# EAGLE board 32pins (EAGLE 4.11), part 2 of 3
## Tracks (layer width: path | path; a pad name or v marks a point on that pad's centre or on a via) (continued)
GND  (via drill 0.61) (continued)
  Top 0.254: 35.55,126.2 35.55,133.19 C2.2 | 35.55,126.2 35.55,122.39 D38.A | 35.55,126.2 40,121.75 D39.A 41.27,121.75 42.54,120.48 43.81,120.48 45.08,119.21 R135.1 45.71,118.58 46.35,117.94 49.52,117.94 50.16,118.58 50.79,118.58 R131.1 | 17.78,67.78 17.78,63.97 D19.A 18.41,63.34 19.68,62.06 20.95,62.06 | 17.78,67.78 D24.A | 20.95,62.06 22.22,60.8 R55.1 | 20.95,62.06 26.67,62.06 27.3,61.43 27.3,60.8 R51.1 | 17.78,67.78 D24.A | R79.1 30.48,70.32 29.84,69.68 27.3,69.68 26.03,68.41 R75.1 24.76,68.41 23.49,67.14 19.68,67.14 18.41,68.41 D24.A | 35.55,65.24 35.55,67.78 D29.A | 35.55,65.24 35.55,63.97 D22.A | 40.63,65.24 40.63,67.78 D28.A | 40.63,65.24 40.63,63.97 D23.A | 43.81,62.06 45.08,60.8 R71.1 | 43.81,62.06 42.54,62.06 41.27,63.34 | D23.A 41.27,63.34 | 43.81,62.06 49.52,62.06 50.16,61.43 50.16,60.8 R67.1 | 41.27,63.34 47.62,69.68 | 47.62,69.68 48.25,70.32 R91.1 | D23.A 41.27,63.34 | 47.62,69.68 52.06,69.68 52.7,70.32 53.34,70.32 R95.1 | 35.55,65.24 40.63,65.24 | 17.78,95.72 17.78,98.26 D32.A 18.41,98.89 19.68,97.62 21.59,97.62 R107.1 25.39,100.8 26.03,100.8 26.67,100.16 29.84,100.16 30.48,100.8 R111.1 | 17.78,95.72 17.78,91.91 D27.A 18.41,91.27 19.68,90 20.95,90 22.22,88.73 R87.1 | 17.78,95.72 13.33,91.27 D26.A 12.69,90.64 10.79,88.73 10.79,70.95 12.69,69.05 D25.A | 35.55,95.72 35.55,98.26 D37.A | 35.55,95.72 35.55,91.91 D30.A | 35.55,95.72 40,91.27 D31.A 41.27,91.27 42.54,90 43.81,90 | 47.62,100.16 45.08,97.62 42.54,97.62 41.27,98.89 D36.A | 47.62,100.16 48.25,100.8 R123.1 | 47.62,100.16 52.06,100.16 52.7,100.8 53.34,100.8 R127.1 | v11.42,106.52 11.42,100.8 12.69,99.53 D33.A | v147.95,35.4 146.05,35.4 145.41,34.76 137.16,34.76 135.88,33.49 134.62,33.49 v130.17,37.94
  Top 0.254: v125.73,37.94 v125.73,48.73 | v116.84,57.62 v116.84,62.7 | 168.91,149.06 175.25,142.71 GND.1 | 43.81,90 45.08,88.73 R103.1 | 43.81,90 49.52,90 50.16,89.37 50.16,88.73 R99.1
  Bottom 0.254: IC9.GND 195.58,128.11 195.58,135.09 185.41,145.25 185.41,145.89 IC10.GND | Q51.S 156.84,45.55 154.94,43.65 D84.A 154.94,42.38 151.12,42.38 149.86,41.11 R276.2 | R11.2 150.49,10 152.4,11.9 154.94,11.9 D6.A | R274.2 130.17,40.48 132.08,42.38 134.62,42.38 D82.A | D75.A 139.69,18.25 139.69,24.6 R272.2 139.69,25.87 139.69,27.14 | D79.A 139.69,33.49 139.69,39.84 R282.2 140.33,40.48 141.6,41.74 142.87,41.74 144.14,43.02 D90.A | R264.2 130.17,25.23 132.08,27.14 134.62,27.14 D72.A | 139.69,27.14 137.16,29.68 Q39.S | D76.A 144.14,12.54 142.87,11.27 141.6,11.27 140.33,10 R268.2 | 139.69,27.14 143.5,27.14 144.14,27.78 D80.A | D107.A 160.02,75.4 158.11,73.49 Q73.S | D99.A 139.69,76.67 139.69,83.02 R296.2 139.69,84.29 139.69,85.56 137.16,88.1 Q69.S | D105.A 149.86,75.4 147.95,73.49 Q67.S 147.31,72.86 149.86,70.32 149.86,69.05 R298.2 | R278.2 130.17,55.72 132.08,57.62 134.62,57.62 D86.A | 140.97,69.05 140.33,68.41 R292.2 | 140.97,69.05 142.87,70.95 144.14,70.95 D100.A | 140.97,69.05 137.16,72.86 Q65.S | R302.2 150.49,83.65 152.4,85.56 154.94,85.56 D110.A | 139.69,93.81 139.69,91.91 D103.A | 139.69,93.81 139.69,98.26 R308.2 | R294.2 130.17,83.65 132.08,85.56 134.62,85.56 D102.A | 139.69,93.81 146.68,93.81 149.22,91.27 D109.A | D117.A 130.17,121.75 131.44,123.02 137.79,123.02 139.06,121.75 D125.A | R310.2 130.17,114.13 132.08,116.04 134.62,116.04 D118.A | D115.A 139.69,107.15 139.69,113.5 R318.2 139.69,114.77 139.69,116.04 | R306.2 130.17,98.89 132.08,100.8 134.62,100.8 D114.A | 139.69,116.04 137.16,118.58 Q85.S | D121.A 149.86,107.15 149.86,113.5 R312.2 149.86,114.77 149.86,116.04
  Bottom 0.254: 149.86,116.04 147.31,118.58 Q93.S | D122.A 154.3,101.43 153.03,100.16 151.76,100.16 150.49,98.89 R314.2 | 149.86,116.04 153.66,116.04 154.3,116.67 D120.A | 139.69,116.04 144.78,116.04 D126.A | 89.53,44.29 90.8,43.02 D47.A | 89.53,44.29 86.99,46.83 83.18,46.83 81.91,45.55 R166.2 | 89.53,44.29 94.61,44.29 95.88,45.55 100.96,45.55 R170.2 | R150.2 81.91,30.32 83.18,31.59 89.53,31.59 90.8,30.32 R162.2 | R146.2 100.96,30.32 95.88,30.32 94.61,29.05 93.34,29.05 92.07,27.78 D42.A | 89.53,13.81 90.8,12.54 D1.A | 89.53,13.81 86.99,16.35 83.18,16.35 81.91,15.08 R142.2 | 89.53,13.81 94.61,13.81 95.88,15.08 100.96,15.08 R154.2 | D40.A 102.23,12.54 103.5,13.81 106.04,13.81 107.31,15.08 111.12,15.08 R14.2 | D5.A 102.23,27.78 103.5,29.05 106.04,29.05 107.31,30.32 111.12,30.32 R158.2 | D44.A 102.23,43.02 103.5,44.29 106.04,44.29 107.31,45.55 111.12,45.55 R186.2 | 80.64,62.06 80.01,62.7 80.01,69.05 81.28,70.32 D51.A | 80.64,62.06 81.28,61.43 R174.2 | 80.64,62.06 84.45,62.06 85.72,60.8 90.8,60.8 R190.2 92.07,60.8 93.34,59.52 94.61,59.52 95.88,60.8 100.96,60.8 R178.2 | 99.69,74.77 93.34,74.77 92.07,73.49 R214.2 | 99.69,74.77 100.96,73.49 R202.2 | 99.69,74.77 104.77,74.77 106.04,73.49 111.12,73.49 R218.2 | D61.A 81.91,116.67 83.18,115.4 85.72,115.4 86.99,114.13 88.26,114.13 90.8,116.67 D65.A | 94.61,120.48 95.88,119.21 100.96,119.21 R242.2 | 94.61,120.48 93.34,120.48 92.07,119.21 R254.2 | 94.61,120.48 104.77,120.48 106.04,119.21 111.12,119.21 R258.2 | 89.53,90 87.62,90 | 87.62,90 83.18,90 81.91,88.73 R206.2 | 89.53,90 90.8,88.73 R222.2 | 89.53,90 94.61,90 95.88,88.73 100.96,88.73 R210.2
  Bottom 0.254: 82.55,104.61 83.18,105.24 86.99,105.24 90.8,101.43 D63.A | 82.55,104.61 81.91,103.97 R230.2 | 110.48,104.61 111.12,103.97 R250.2 | 110.48,104.61 109.85,105.24 103.5,105.24 102.23,103.97 R234.2 | R246.2 92.07,103.97 93.34,105.24 97.15,105.24 100.96,101.43 D60.A | 87.62,90 87.62,93.18 82.55,98.26 82.55,104.61 | 110.48,104.61 v110.48,107.78 | R226.2 111.12,88.73 106.04,88.73 104.77,87.46 103.5,87.46 102.23,86.19 D54.A | R1.1 25.39,11.9 22.22,8.73 19.68,8.73 18.41,10 D2.A | D12.A 40,10 38.73,11.27 37.46,11.27 36.19,10 D13.A | R47.1 31.11,43.02 33.65,40.48 34.92,40.48 D21.A | R115.1 28.57,119.21 28.57,119.85 29.21,120.48 33.65,120.48 34.92,121.75 D38.A | D18.A 12.69,63.97 12.69,67.78 D25.A | R79.1 31.11,70.95 33.65,68.41 34.92,68.41 D29.A | D26.A 12.69,91.91 12.69,98.26 D33.A | R83.1 27.94,88.1 27.3,88.1 26.67,87.46 23.49,87.46 22.86,88.1 R87.1 | D36.A 40,98.89 38.73,100.16 37.46,100.16 36.19,98.89 D37.A 34.92,98.89 33.65,98.89 31.11,101.43 R111.1 | v11.42,106.52 11.42,119.85 12.69,121.12 D34.A | v59.05,8.73 57.78,8.73 53.97,12.54 R31.1 | v147.95,35.4 149.86,33.49 D69.A | v130.17,37.94 v125.73,37.94 | v125.73,48.73 v116.84,57.62 | v116.84,62.7 112.39,58.26 D50.A
  pour Top (rank 2): 200.66,129.38 190.5,129.38 190.5,144.62 200.66,144.62
H1  (via drill 0.61)
  Top 0.254: 105.41,24.6 104.14,23.33 64.13,23.33 54.6,32.86 53.97,32.86 R36.1 | 105.41,24.6 107.31,26.51 Q9.D | Q46.D 160.65,29.05 161.92,27.78 163.19,27.78 165.09,29.68 Q45.D | v183.51,31.59 182.24,31.59 179.7,29.05 167,29.05 166.37,28.41 v166.37,26.51 | v106.04,23.96 105.41,24.6 | v118.74,15.08 127,6.82 167.63,6.82 185.41,24.6 189.22,24.6 190.5,25.87 v190.5,36.03
  Bottom 0.254: 189.22,37.3 188.59,36.66 183.51,36.66 180.97,34.12 v183.51,31.59 | 189.22,37.3 193.03,41.11 193.03,105.88 170.81,128.11 167,128.11 165.09,130.01 127,130.01 120.65,136.36 120.65,137.63 119.38,138.9 SIDE1.16 | v166.37,26.51 166.37,24.6 165.09,23.33 162.56,23.33 161.28,24.6 161.28,27.14 160.02,28.41 Q46.D | v106.04,23.96 109.85,23.96 v118.74,15.08 | 189.22,37.3 v190.5,36.03
H2  (via drill 0.61)
  Top 0.254: 67.31,72.86 73.02,67.14 84.45,67.14 86.99,69.68 Q23.D 87.62,69.05 v89.53,67.14 | 67.31,72.86 66.04,74.13 62.22,74.13 55.24,67.14 50.16,67.14 48.89,68.41 R92.1 | v63.49,125.56 64.77,125.56 v67.94,122.39 | 67.31,72.86 v73.02,78.57 | v146.05,64.6 v148.59,67.14 | v118.11,71.59 v125.09,64.6
  Bottom 0.254: 154.94,72.86 153.03,70.95 151.76,70.95 150.49,72.22 Q74.D | 154.94,72.86 Q73.D 154.94,72.86 | v63.49,125.56 59.68,129.38 59.68,137.63 58.41,138.9 SIDE2.12 | v67.94,122.39 67.94,117.94 78.1,107.78 79.37,107.78 80.01,107.15 80.01,98.26 74.93,93.18 74.93,90.64 74.29,90 73.02,90 72.39,89.37 72.39,79.21 v73.02,78.57 | 154.94,72.86 156.21,71.59 156.21,67.78 155.57,67.14 v148.59,67.14 | v125.09,64.6 v146.05,64.6 | v118.11,71.59 113.03,66.51 90.17,66.51 v89.53,67.14
J1  (via drill 0.61)
  Top 0.254: v66.67,25.23 64.77,27.14 64.77,30.95 64.13,31.59 58.41,31.59 56.51,33.49 54.6,33.49 53.97,34.12 50.16,34.12 48.89,32.86 R40.1 | v158.75,142.71 v162.56,142.71 | v196.21,25.23 172.72,1.74 119.38,1.74 | 119.38,1.74 85.09,1.74 81.91,4.92 86.99,10 88.26,10 88.9,10.63 v88.9,15.71 | v133.98,36.66 v135.88,34.76 | v125.09,36.66 123.82,35.4 v123.82,30.32 | 119.38,1.74 v119.38,3.65
  Bottom 0.254: Q47.D 144.78,29.68 142.87,27.78 141.6,27.78 140.33,29.05 Q48.D 139.69,29.68 139.69,30.95 v135.88,34.76 | v66.67,25.23 67.94,23.96 84.45,23.96 86.99,26.51 Q10.D 87.62,25.87 87.62,16.98 v88.9,15.71 | v158.75,142.71 127,142.71 124.45,140.17 SIDE1.20 | v162.56,142.71 196.21,109.05 v196.21,25.23 | v125.09,36.66 v133.98,36.66 | v123.82,30.32 123.82,6.18 120.65,3.01 120.01,3.01 v119.38,3.65
J2  (via drill 0.61)
  Top 0.254: Q75.D 165.09,72.86 163.19,70.95 161.92,70.95 160.65,72.22 Q76.D 160.02,72.86 157.47,75.4 157.47,76.03 156.21,77.3 152.4,77.3 151.12,78.57 v147.95,78.57 | v99.69,134.46 92.07,142.08 64.13,142.08 61.59,139.53 SIDE2.14 | v104.14,126.2 118.11,126.2 v119.38,124.93 | v117.47,115.4 v120.65,118.58 | v126.36,107.78 126.36,90 127,89.37 127,84.92 125.09,83.02 | 125.09,83.02 122.55,80.48 v115.56,80.48 | v130.17,78.57 v145.41,78.57 | 125.09,83.02 v125.73,83.02
  Bottom 0.254: 112.39,77.3 113.03,76.67 113.03,72.86 112.39,72.22 111.12,72.22 108.58,69.68 Q24.D | 112.39,77.3 75.56,77.3 74.93,76.67 74.93,72.86 74.29,72.22 64.77,72.22 62.22,69.68 60.32,69.68 56.51,73.49 R96.1 | v99.69,134.46 104.77,129.38 104.77,126.83 v104.14,126.2 | v119.38,124.93 119.38,119.85 v120.65,118.58 | v117.47,115.4 125.09,107.78 v126.36,107.78 | 112.39,77.3 v115.56,80.48 | v145.41,78.57 v147.95,78.57 | v125.73,83.02 v130.17,78.57
K1  (via drill 0.61)
  Top 0.254: v194.94,106.52 196.21,105.24 196.21,26.51 173.35,3.65 121.28,3.65 v120.65,4.28 | v120.65,29.05 120.65,38.57 121.28,39.2 | 121.28,39.2 v123.82,39.2 | v81.28,36.03 82.55,36.03 v83.81,34.76 | v117.47,37.94 118.74,39.2 121.28,39.2
  Bottom 0.254: 76.83,40.48 77.47,41.11 Q11.D | 76.83,40.48 73.02,36.66 62.86,36.66 60.95,34.76 30.48,34.76 25.39,39.84 R44.1 | Q49.D 134.62,44.92 132.71,43.02 131.44,43.02 130.17,44.29 Q50.D 128.9,44.29 v123.82,39.2 | v194.94,106.52 160.02,141.44 127,141.44 125.73,140.17 125.73,138.9 125.09,138.27 123.82,138.27 122.55,139.53 SIDE1.18 | v120.65,4.28 120.65,5.55 122.55,7.46 122.55,25.23 120.65,27.14 v120.65,29.05 | v81.28,36.03 76.83,40.48 | v83.81,34.76 92.07,34.76 94.61,37.3 116.84,37.3 v117.47,37.94
K2  (via drill 0.61)
  Top 0.254: v78.73,89.37 76.2,89.37 74.29,87.46 69.21,87.46 v64.77,83.02 | 114.3,100.8 114.3,99.53 v114.93,98.89 | 114.3,100.8 114.3,113.5 118.11,117.31 118.11,118.58 113.03,123.66 104.14,123.66 88.26,139.53 88.26,140.81 87.62,141.44 66.04,141.44 64.13,139.53 SIDE2.16 | v110.48,97.62 110.48,94.45 107.95,91.91 107.95,90.64 107.31,90 103.5,90 102.87,89.37 102.87,83.02 102.23,82.38 93.34,82.38 92.7,83.02 92.7,84.29 92.07,84.92 88.26,84.92 Q25.D | v137.79,92.54 v146.68,92.54 | v135.88,94.45 134.62,94.45 v132.08,96.99 | v123.82,105.24 118.74,105.24 114.3,100.8
  Bottom 0.254: Q77.D 154.94,88.1 153.03,86.19 151.76,86.19 150.49,87.46 Q78.D 149.86,88.1 149.86,89.37 v146.68,92.54 | v78.73,89.37 78.73,86.83 80.64,84.92 86.99,84.92 Q25.D | v64.77,83.02 56.51,91.27 53.97,91.27 R100.1 | v114.93,98.89 113.66,98.89 112.39,97.62 v110.48,97.62 | v135.88,94.45 v137.79,92.54 | v132.08,96.99 130.81,98.26 130.17,97.62 128.9,97.62 123.82,102.7 v123.82,105.24
L1  (via drill 0.61)
  Top 0.254: 34.28,47.46 36.82,50 64.77,50 v65.4,49.37 73.02,41.74 75.56,41.74 78.73,38.57 95.25,38.57 97.79,41.11 Q12.D | 34.28,47.46 33.02,46.19 R48.1 | v125.09,133.19 108.58,133.19 107.31,134.46 100.96,134.46 92.7,142.71 50.79,142.71 v49.52,141.44 | v17.78,133.82 8.88,124.93 8.88,42.38 v13.33,37.94 | v22.86,37.3 29.21,37.3 34.28,42.38 34.28,47.46 | v130.81,53.81 v133.34,51.27 | v116.2,46.83 v124.45,55.08
  Bottom 0.254: Q51.D 154.94,44.92 153.03,43.02 151.76,43.02 150.49,44.29 Q52.D 149.86,44.92 147.31,47.46 147.31,48.09 144.14,51.27 v133.34,51.27 | v125.09,133.19 128.27,136.36 128.27,137.63 129.53,138.9 SIDE1.24 | v49.52,141.44 43.81,141.44 41.9,143.34 27.3,143.34 v17.78,133.82 | v13.33,37.94 22.22,37.94 v22.86,37.3 | v130.81,53.81 127.63,53.81 126.36,55.08 v124.45,55.08 | v116.2,46.83 114.93,46.83 112.39,49.37 v65.4,49.37
L2  (via drill 0.61)
  Top 0.254: Q80.D 160.65,87.46 161.92,86.19 163.19,86.19 165.09,88.1 Q79.D | v66.04,80.48 102.87,80.48 107.31,84.92 Q26.D 107.95,85.56 110.48,88.1 v110.48,90 | v113.66,121.75 112.39,123.02 103.5,123.02 87.62,138.9 87.62,140.17 86.99,140.81 67.94,140.81 66.67,139.53 SIDE2.18 | 113.66,96.35 113.66,92.54 v114.3,91.91 | 113.66,96.35 v113.66,115.4 | v161.28,94.45 143.5,94.45 140.97,96.99 v133.98,96.99 | v117.47,96.35 113.66,96.35
  Bottom 0.254: v66.04,80.48 56.51,90 50.16,90 48.89,91.27 R104.1 | v113.66,115.4 v113.66,121.75 | v114.3,91.91 112.39,90 v110.48,90 | v161.28,94.45 165.09,90.64 165.09,89.37 Q79.D | v133.98,96.99 132.71,95.72 124.45,95.72 122.55,97.62 118.74,97.62 v117.47,96.35
M1  (via drill 0.61)
  Top 0.254: 71.12,51.27 76.83,56.98 Q13.D | 71.12,51.27 39.36,51.27 33.02,57.62 33.02,62.06 31.75,63.34 31.11,63.34 R52.1 | v129.53,128.74 v135.88,135.09 | v123.19,116.04 123.19,114.77 121.28,112.86 121.28,109.05 125.09,105.24 125.09,86.83 v124.45,86.19 | v71.75,50.63 71.12,51.27 | v114.93,48.09 114.93,49.37 v123.19,57.62
  Bottom 0.254: Q53.D 134.62,60.16 132.71,58.26 131.44,58.26 130.17,59.52 Q54.D 128.9,59.52 126.36,56.98 124.45,58.89 | v135.88,135.09 135.88,137.63 134.62,138.9 SIDE1.28 | v129.53,128.74 123.19,122.39 v123.19,116.04 | v124.45,86.19 123.82,85.56 123.82,59.52 124.45,58.89 | v71.75,50.63 112.39,50.63 v114.93,48.09 | 124.45,58.89 v123.19,57.62
M2  (via drill 0.61)
  Top 0.254: v64.77,124.29 67.94,121.12 v67.94,112.23 | v130.81,96.99 130.81,100.8 129.53,102.07 Q82.D
  Bottom 0.254: Q82.D 130.17,102.7 131.44,101.43 132.71,101.43 134.62,103.34 Q81.D | 76.83,100.16 71.75,95.08 29.84,95.08 26.03,98.89 R108.1 | 76.83,100.16 Q27.D 76.83,100.16 | v64.77,124.29 67.31,126.83 67.31,137.63 68.58,138.9 SIDE2.20 68.58,140.17 70.48,142.08 94.61,142.08 107.31,129.38 105.41,127.47 105.41,121.12 106.04,120.48 112.39,120.48 113.03,119.85 113.03,116.04 112.39,115.4 123.19,104.61 123.19,102.07 128.27,96.99 v130.81,96.99 | v67.94,112.23 64.77,109.05 64.77,108.42 73.02,100.16 76.83,100.16
N1  (via drill 0.61)
  Top 0.254: 63.49,54.45 54.6,54.45 52.06,51.91 40,51.91 v38.73,53.18 | 63.49,54.45 v71.12,54.45 | v170.18,130.01 170.18,128.74 191.77,107.15 v191.77,98.26 | v170.18,55.08 164.46,49.37 v156.84,49.37 | 63.49,54.45 63.49,72.22 v62.86,72.86 | v62.22,83.02 62.22,89.37 62.86,90 v67.94,90 | v70.48,92.54 70.48,120.48 73.66,123.66 v87.62,123.66 | v102.87,128.74 105.41,128.74 106.04,128.11 123.82,128.11 v127,131.28
  Bottom 0.254: v71.12,54.45 86.99,54.45 89.53,56.98 97.15,56.98 Q14.D | v38.73,53.18 38.09,53.18 33.02,58.26 33.02,60.8 31.75,62.06 27.3,62.06 26.03,63.34 R56.1 | 151.12,58.89 151.76,58.26 153.03,58.26 154.94,60.16 Q55.D | 151.12,58.89 150.49,59.52 Q56.D | 130.81,140.81 159.38,140.81 v170.18,130.01 | 130.81,140.81 128.9,140.81 127.63,139.53 SIDE1.22 | v191.77,98.26 191.77,76.67 v170.18,55.08 | v156.84,49.37 151.12,55.08 151.12,58.89 | v62.86,72.86 62.86,76.67 62.22,77.3 v62.22,83.02 | v70.48,92.54 v67.94,90 | v87.62,123.66 97.79,123.66 v102.87,128.74 | v127,131.28 127,132.55 130.81,136.36 130.81,140.81
N2  (via drill 0.61)
  Top 0.254: v36.82,120.48 34.92,120.48 34.28,121.12 v34.28,132.55 | v64.77,138.27 69.21,138.27 | 69.21,138.27 70.48,139.53 SIDE2.22 | v86.99,133.19 86.99,135.72 87.62,136.36 87.62,137.63 86.99,138.27 69.21,138.27
  Bottom 0.254: 99.69,98.89 103.5,95.08 135.25,95.08 138.43,98.26 138.43,100.8 139.06,101.43 | 99.69,98.89 98.42,100.16 Q28.D | 139.06,101.43 139.69,102.07 Q84.D | 139.06,101.43 142.87,101.43 144.78,103.34 Q83.D | v36.82,120.48 36.82,113.5 33.02,109.69 33.02,104.61 R112.1 | v34.28,132.55 48.25,132.55 52.06,136.36 52.06,137.63 52.7,138.27 53.97,138.27 54.6,138.9 54.6,140.17 55.24,140.81 64.13,140.81 64.77,140.17 v64.77,138.27 | 99.69,98.89 100.96,100.16 102.23,100.16 102.87,100.8 102.87,102.07 102.23,102.7 100.96,102.7 97.79,105.88 97.79,107.15 93.98,110.96 82.55,110.96 80.01,113.5 80.01,119.85 80.64,120.48 84.45,120.48 85.09,121.12 85.09,131.28 v86.99,133.19
N$1
  pour Top: 177.8,129.38 187.96,129.38 187.96,144.62 177.8,144.62
N$2
  Top 0.254: R321.2 15.23,140.17 15.23,141.44 THR.3
N$3
  Top 0.254: R323.1 27.94,140.17 27.94,141.44 THR.1
N$4
  Top 0.254: Q3.G 105.41,12.54 104.77,12.54 D132.A 104.14,13.17 104.14,14.44 R2.1
N$5
  Top 0.254: R10.2 154.3,10 153.03,10 R11.1 152.4,10.63 152.4,13.17 Q2.S
N$7
  Top 0.254: Q4.G 85.09,12.54 84.45,12.54 D136.A 83.81,13.17 83.81,14.44 R4.1
N$8
  Top 0.254: Q4.S 87.62,14.44 87.62,15.71 88.9,16.98 R8.2 89.53,17.62 90.8,17.62 R9.1
N$12
  Top 0.254: Q5.G 74.93,12.54 74.29,12.54 D135.A 73.66,13.17 73.66,14.44 R139.1
N$13
  Top 0.254: IC1.5 25.39,16.35 25.39,15.71 R1.2
  Bottom 0.254: R3.2 28.57,10 29.84,10 31.75,11.9 31.75,13.17 31.11,13.81 26.03,13.81 25.39,14.44 R1.2
N$14
  Top 0.254: IC1.4 22.86,16.35 22.86,15.71 JP1.1
N$15
  Top 0.254: Q5.S 78.1,13.81 81.28,16.98 R142.1 80.64,17.62 79.37,17.62 R141.2
N$16
  Top 0.254: Q3.S 108.58,13.81 111.76,16.98 R14.1 111.12,17.62 109.85,17.62 R13.2
N$18
  Top 0.254: IC1.2 17.78,16.35 17.78,15.71 R7.2
  Bottom 0.254: R6.1 19.68,12.54 17.78,14.44 R7.2
N$20
  Top 0.254: IC1.7 30.48,16.35 30.48,15.71 R15.2
  Bottom 0.254: R16.2 33.02,13.17 31.11,15.08 R15.2
N$21
  Top 0.254: IC1.6 27.94,16.35 27.94,15.71 JP3.1
N$22
  Top 0.254: R17.1 13.33,15.08 14.6,15.08 R18.2 15.23,15.71 15.23,16.35 IC1.1
N$23
  Top 0.254: IC1.9 27.94,26.51 27.94,27.14 R19.2
  Bottom 0.254: R20.2 28.57,32.86 29.84,31.59 31.75,31.59 32.38,30.95 32.38,29.68 31.75,29.05 28.57,29.05 27.94,28.41 R19.2
N$24
  Top 0.254: IC1.8 30.48,26.51 30.48,27.14 JP4.1
N$25
  Top 0.254: IC1.14 15.23,26.51 15.23,27.14 R22.2 14.6,27.78 13.33,27.78 R21.1
N$26
  Top 0.254: IC1.11 22.86,26.51 22.86,27.14 R23.2
  Bottom 0.254: R24.2 22.86,32.22 21.59,30.95 21.59,29.68 22.86,28.41 R23.2
N$27
  Top 0.254: IC1.10 25.39,26.51 25.39,27.14 JP5.1
N$28
  Top 0.254: IC1.13 17.78,26.51 17.78,27.14 R26.2 18.41,27.78 19.68,27.78 R25.1
N$35
  Top 0.254: R28.2 51.43,10 52.7,10 54.6,11.9 54.6,13.17 53.97,13.81 48.89,13.81 48.25,14.44 R27.2 48.25,15.71 48.25,16.35 IC2.5
N$36
  Top 0.254: IC2.4 45.71,16.35 45.71,15.71 JP6.1
N$38
  Top 0.254: IC2.2 40.63,16.35 40.63,15.71 R30.2
  Bottom 0.254: R29.1 42.54,12.54 40.63,14.44 R30.2
N$39
  Top 0.254: R32.2 55.88,13.17 53.97,15.08 R31.2 53.34,15.71 53.34,16.35 IC2.7
N$40
  Top 0.254: IC2.6 50.79,16.35 50.79,15.71 JP7.1
N$41
  Top 0.254: R33.1 36.19,15.08 37.46,15.08 R34.2 38.09,15.71 38.09,16.35 IC2.1
N$42
  Top 0.254: IC2.9 50.79,26.51 50.79,27.14 R35.2 50.79,28.41 51.43,29.05 54.6,29.05 55.24,29.68 55.24,30.95 54.6,31.59 52.7,31.59 51.43,32.86 R36.2
N$43
  Top 0.254: IC2.8 53.34,26.51 53.34,27.14 JP8.1
N$44
  Top 0.254: IC2.14 38.09,26.51 38.09,27.14 R38.2 37.46,27.78 36.19,27.78 R37.1
N$45
  Top 0.254: IC2.11 45.71,26.51 45.71,27.14 R39.2
  Bottom 0.254: R40.2 45.71,32.22 44.45,30.95 44.45,29.68 45.71,28.41 R39.2
N$46
  Top 0.254: IC2.10 48.25,26.51 48.25,27.14 JP9.1
N$47
  Top 0.254: IC2.13 40.63,26.51 40.63,27.14 R42.2 41.27,27.78 42.54,27.78 R41.1
N$55
  Top 0.254: R44.2 28.57,40.48 29.84,40.48 31.75,42.38 31.75,43.65 31.11,44.29 26.03,44.29 25.39,44.92 R43.2 25.39,46.19 25.39,46.83 IC3.5
N$56
  Top 0.254: IC3.4 22.86,46.83 22.86,46.19 JP10.1
N$58
  Top 0.254: IC3.2 17.78,46.83 17.78,46.19 R46.2
  Bottom 0.254: R45.1 19.68,43.02 17.78,44.92 R46.2
N$59
  Top 0.254: IC3.7 30.48,46.83 30.48,46.19 R47.2
  Bottom 0.254: R48.2 32.38,43.02 30.48,44.92 R47.2
N$60
  Top 0.254: IC3.6 27.94,46.83 27.94,46.19 JP11.1
N$61
  Top 0.254: R49.1 13.33,45.55 14.6,45.55 R50.2 15.23,46.19 15.23,46.83 IC3.1
N$62
  Top 0.254: IC3.9 27.94,56.98 27.94,57.62 R51.2 27.94,58.89 28.57,59.52 31.75,59.52 32.38,60.16 32.38,61.43 31.75,62.06 29.84,62.06 28.57,63.34 R52.2
N$63
  Top 0.254: IC3.8 30.48,56.98 30.48,57.62 JP12.1
N$64
  Top 0.254: IC3.14 15.23,56.98 15.23,57.62 R54.2 14.6,58.26 13.33,58.26 R53.1
N$65
  Top 0.254: IC3.11 22.86,56.98 22.86,57.62 R55.2
  Bottom 0.254: R56.2 22.86,62.7 21.59,61.43 21.59,60.16 22.86,58.89 R55.2
N$66
  Top 0.254: IC3.10 25.39,56.98 25.39,57.62 JP13.1
N$67
  Top 0.254: IC3.13 17.78,56.98 17.78,57.62 R58.2 18.41,58.26 19.68,58.26 R57.1
N$75
  Top 0.254: R59.2 51.43,40.48 52.7,40.48 54.6,42.38 54.6,43.65 53.97,44.29 48.89,44.29 48.25,44.92 R60.2 48.25,46.19 48.25,46.83 IC4.5
N$76
  Top 0.254: IC4.4 45.71,46.83 45.71,46.19 JP14.1
N$78
  Top 0.254: IC4.2 40.63,46.83 40.63,46.19 R62.2
  Bottom 0.254: R61.1 42.54,43.02 40.63,44.92 R62.2
N$79
  Top 0.254: IC4.7 53.34,46.83 53.34,46.19 R63.2
  Bottom 0.254: R64.2 55.24,43.02 53.34,44.92 R63.2
N$80
  Top 0.254: IC4.6 50.79,46.83 50.79,46.19 JP15.1
N$81
  Top 0.254: R65.1 36.19,45.55 37.46,45.55 R66.2 38.09,46.19 38.09,46.83 IC4.1
N$82
  Top 0.254: IC4.9 50.79,56.98 50.79,57.62 R67.2 50.79,58.89 51.43,59.52 54.6,59.52 55.24,60.16 55.24,61.43 54.6,62.06 52.7,62.06 51.43,63.34 R68.2
N$83
  Top 0.254: IC4.8 53.34,56.98 53.34,57.62 JP16.1
N$84
  Top 0.254: IC4.14 38.09,56.98 38.09,57.62 R70.2 37.46,58.26 36.19,58.26 R69.1
N$85
  Top 0.254: IC4.11 45.71,56.98 45.71,57.62 R71.2
  Bottom 0.254: R72.2 45.71,62.7 44.45,61.43 44.45,60.16 45.71,58.89 R71.2
N$86
  Top 0.254: IC4.10 48.25,56.98 48.25,57.62 JP17.1
N$87
  Top 0.254: IC4.13 40.63,56.98 40.63,57.62 R74.2 41.27,58.26 42.54,58.26 R73.1
N$95
  Top 0.254: R75.2 28.57,68.41 29.84,68.41 31.75,70.32 31.75,71.59 31.11,72.22 26.03,72.22 25.39,72.86 R76.2 25.39,74.13 25.39,74.77 IC5.5
N$96
  Top 0.254: IC5.4 22.86,74.77 22.86,74.13 JP18.1
N$98
  Top 0.254: R77.1 19.68,70.95 17.78,72.86 R78.2 17.78,74.13 17.78,74.77 IC5.2
N$99
  Top 0.254: IC5.7 30.48,74.77 30.48,74.13 R79.2
  Bottom 0.254: R80.2 32.38,70.95 30.48,72.86 R79.2
N$100
  Top 0.254: IC5.6 27.94,74.77 27.94,74.13 JP19.1
N$101
  Top 0.254: R81.1 13.33,73.49 14.6,73.49 R82.2 15.23,74.13 15.23,74.77 IC5.1
N$102
  Top 0.254: IC5.9 27.94,84.92 27.94,85.56 R83.2 27.94,86.83 28.57,87.46 31.75,87.46 32.38,88.1 32.38,89.37 31.75,90 29.84,90 28.57,91.27 R84.2
N$103
  Top 0.254: IC5.8 30.48,84.92 30.48,85.56 JP20.1
N$104
  Top 0.254: IC5.14 15.23,84.92 15.23,85.56 R86.2 14.6,86.19 13.33,86.19 R85.1
N$105
  Top 0.254: IC5.11 22.86,84.92 22.86,85.56 R87.2
  Bottom 0.254: R88.2 22.86,90.64 21.59,89.37 21.59,88.1 22.86,86.83 R87.2
N$106
  Top 0.254: IC5.10 25.39,84.92 25.39,85.56 JP21.1
N$107
  Top 0.254: IC5.13 17.78,84.92 17.78,85.56 R90.2 18.41,86.19 19.68,86.19 R89.1
N$115
  Top 0.254: R92.2 51.43,68.41 52.7,68.41 54.6,70.32 54.6,71.59 53.97,72.22 48.89,72.22 48.25,72.86 R91.2 48.25,74.13 48.25,74.77 IC6.5
N$116
  Top 0.254: IC6.4 45.71,74.77 45.71,74.13 JP22.1
N$118
  Top 0.254: IC6.2 40.63,74.77 40.63,74.13 R94.2
  Bottom 0.254: R93.1 42.54,70.95 40.63,72.86 R94.2
N$119
  Top 0.254: R96.2 55.88,71.59 53.97,73.49 R95.2 53.34,74.13 53.34,74.77 IC6.7
N$120
  Top 0.254: IC6.6 50.79,74.77 50.79,74.13 JP23.1
N$121
  Top 0.254: R97.1 36.19,73.49 37.46,73.49 R98.2 38.09,74.13 38.09,74.77 IC6.1
N$122
  Top 0.254: IC6.9 50.79,84.92 50.79,85.56 R99.2 50.79,86.83 51.43,87.46 54.6,87.46 55.24,88.1 55.24,89.37 54.6,90 52.7,90 51.43,91.27 R100.2
N$123
  Top 0.254: IC6.8 53.34,84.92 53.34,85.56 JP24.1
N$124
  Top 0.254: R101.1 36.19,86.19 37.46,86.19 R102.2 38.09,85.56 38.09,84.92 IC6.14
N$125
  Top 0.254: IC6.11 45.71,84.92 45.71,85.56 R103.2
  Bottom 0.254: R104.2 45.71,90.64 44.45,89.37 44.45,88.1 45.71,86.83 R103.2
N$126
  Top 0.254: IC6.10 48.25,84.92 48.25,85.56 JP25.1
N$127
  Top 0.254: IC6.13 40.63,84.92 40.63,85.56 R106.2 41.27,86.19 42.54,86.19 R105.1
N$135
  Top 0.254: R108.2 28.57,98.89 29.84,98.89 31.75,100.8 31.75,102.07 31.11,102.7 26.03,102.7 25.39,103.34 R107.2 25.39,104.61 25.39,105.24 IC7.5
N$136
  Top 0.254: IC7.4 22.86,105.24 22.86,104.61 JP26.1
N$138
  Top 0.254: IC7.2 17.78,105.24 17.78,104.61 R110.2
  Bottom 0.254: R109.1 19.68,101.43 17.78,103.34 R110.2
N$139
  Top 0.254: IC7.7 30.48,105.24 30.48,104.61 R111.2
  Bottom 0.254: R112.2 32.38,101.43 30.48,103.34 R111.2
N$140
  Top 0.254: IC7.6 27.94,105.24 27.94,104.61 JP27.1
N$141
  Top 0.254: R113.1 13.33,103.97 14.6,103.97 R114.2 15.23,104.61 15.23,105.24 IC7.1
N$142
  Top 0.254: IC7.9 27.94,115.4 27.94,116.04 R115.2 27.94,117.31 28.57,117.94 31.75,117.94 32.38,118.58 32.38,119.85 31.75,120.48 29.84,120.48 28.57,121.75 R116.2
N$143
  Top 0.254: IC7.8 30.48,115.4 30.48,116.04 JP28.1
N$144
  Top 0.254: IC7.14 15.23,115.4 15.23,116.04 R118.2 14.6,116.67 13.33,116.67 R117.1
N$145
  Top 0.254: IC7.11 22.86,115.4 22.86,116.04 R119.2
  Bottom 0.254: R120.2 22.86,121.12 21.59,119.85 21.59,118.58 22.86,117.31 R119.2
N$146
  Top 0.254: IC7.10 25.39,115.4 25.39,116.04 JP29.1
N$147
  Top 0.254: IC7.13 17.78,115.4 17.78,116.04 R122.2 18.41,116.67 19.68,116.67 R121.1
N$155
  Top 0.254: R124.2 51.43,98.89 52.7,98.89 54.6,100.8 54.6,102.07 53.97,102.7 48.89,102.7 48.25,103.34 R123.2 48.25,104.61 48.25,105.24 IC8.5
N$156
  Top 0.254: IC8.4 45.71,105.24 45.71,104.61 JP30.1
N$158
  Top 0.254: IC8.2 40.63,105.24 40.63,104.61 R126.2
  Bottom 0.254: R125.1 42.54,101.43 40.63,103.34 R126.2
N$159
  Top 0.254: IC8.7 53.34,105.24 53.34,104.61 R127.2
  Bottom 0.254: R128.2 55.24,101.43 53.34,103.34 R127.2
N$160
  Top 0.254: IC8.6 50.79,105.24 50.79,104.61 JP31.1
N$161
  Top 0.254: R129.1 36.19,103.97 37.46,103.97 R130.2 38.09,104.61 38.09,105.24 IC8.1
N$162
  Top 0.254: IC8.9 50.79,115.4 50.79,116.04 R131.2 50.79,117.31 51.43,117.94 54.6,117.94 55.24,118.58 55.24,119.85 54.6,120.48 52.7,120.48 51.43,121.75 R132.2
N$163
  Top 0.254: IC8.8 53.34,115.4 53.34,116.04 JP32.1
N$164
  Top 0.254: IC8.14 38.09,115.4 38.09,116.04 R134.2 37.46,116.67 36.19,116.67 R133.1
N$165
  Top 0.254: IC8.11 45.71,115.4 45.71,116.04 R135.2
  Bottom 0.254: R136.2 45.71,121.12 44.45,119.85 44.45,118.58 45.71,117.31 R135.2
N$166
  Top 0.254: IC8.10 48.25,115.4 48.25,116.04 JP33.1
N$167
  Top 0.254: IC8.13 40.63,115.4 40.63,116.04 R138.2 41.27,116.67 42.54,116.67 R137.1
N$177
  Top 0.254: Q6.G 95.25,27.78 94.61,27.78 D134.A 93.98,28.41 93.98,29.68 R143.1
N$178
  Top 0.254: Q6.S 98.42,29.05 101.59,32.22 R146.1 100.96,32.86 99.69,32.86 R145.2
N$181
  Top 0.254: Q7.G 74.93,27.78 74.29,27.78 D133.A 73.66,28.41 73.66,29.68 R147.1
N$182
  Top 0.254: Q7.S 78.1,29.05 81.28,32.22 R150.1 80.64,32.86 79.37,32.86 R149.2
N$186
  Top 0.254: Q8.G 95.25,12.54 94.61,12.54 D131.A 93.98,13.17 93.98,14.44 R151.1
N$187
  Top 0.254: Q8.S 98.42,13.81 101.59,16.98 R154.1 100.96,17.62 99.69,17.62 R153.2
N$190
  Top 0.254: Q9.G 105.41,27.78 104.77,27.78 D130.A 104.14,28.41 104.14,29.68 R155.1
N$191
  Top 0.254: Q9.S 108.58,29.05 111.76,32.22 R158.1 111.12,32.86 109.85,32.86 R157.2
N$194
  Top 0.254: Q10.G 85.09,27.78 84.45,27.78 D129.A 83.81,28.41 83.81,29.68 R159.1
N$195
  Top 0.254: Q10.S 88.26,29.05 91.44,32.22 R162.1 90.8,32.86 89.53,32.86 R161.2
N$198
  Top 0.254: Q11.G 74.93,43.02 74.29,43.02 D144.A 73.66,43.65 73.66,44.92 R163.1
N$199
  Top 0.254: Q11.S 78.1,44.29 81.28,47.46 R166.1 80.64,48.09 79.37,48.09 R165.2
N$202
  Top 0.254: Q12.G 95.25,43.02 94.61,43.02 D143.A 93.98,43.65 93.98,44.92 R167.1
N$203
  Top 0.254: Q12.S 98.42,44.29 101.59,47.46 R170.1 100.96,48.09 99.69,48.09 R169.2
N$206
  Top 0.254: Q13.G 74.93,58.26 74.29,58.26 D142.A 73.66,58.89 73.66,60.16 R171.1
N$207
  Top 0.254: Q13.S 78.1,59.52 81.28,62.7 R174.1 80.64,63.34 79.37,63.34 R173.2
N$210
  Top 0.254: Q14.G 95.25,58.26 94.61,58.26 D141.A 93.98,58.89 93.98,60.16 R175.1
N$211
  Top 0.254: Q14.S 98.42,59.52 101.59,62.7 R178.1 100.96,63.34 99.69,63.34 R177.2
N$214
  Top 0.254: Q15.G 85.09,43.02 84.45,43.02 D140.A 83.81,43.65 83.81,44.92 R179.1
N$215
  Top 0.254: 89.53,46.83 90.8,48.09 R182.1 | 89.53,46.83 87.62,44.92 Q15.S | 89.53,46.83 88.9,47.46 R181.2
N$218
  Top 0.254: Q16.G 105.41,43.02 104.77,43.02 D139.A 104.14,43.65 104.14,44.92 R183.1
N$219
  Top 0.254: Q16.S 108.58,44.29 111.76,47.46 R186.1 111.12,48.09 109.85,48.09 R185.2
N$222
  Top 0.254: Q17.G 85.09,58.26 84.45,58.26 D138.A 83.81,58.89 83.81,60.16 R187.1
N$223
  Top 0.254: Q17.S 88.26,59.52 91.44,62.7 R190.1 90.8,63.34 89.53,63.34 R189.2
N$226
  Top 0.254: Q18.G 105.41,58.26 104.77,58.26 D137.A 104.14,58.89 104.14,60.16 R191.1
N$227
  Top 0.254: Q18.S 108.58,59.52 109.85,58.26 111.12,59.52 109.22,61.43 109.22,62.7 R193.2 109.85,63.34 111.12,63.34 R194.1
N$230
  Top 0.254: Q19.G 74.93,70.95 74.29,70.95 D152.A 73.66,71.59 73.66,72.86 R195.1
N$231
  Top 0.254: Q19.S 78.1,72.22 81.28,75.4 R198.1 80.64,76.03 79.37,76.03 R197.2
N$234
  Top 0.254: Q20.G 95.25,70.95 94.61,70.95 D151.A 93.98,71.59 93.98,72.86 R199.1
N$235
  Top 0.254: 99.69,74.77 100.96,76.03 R202.1 | 99.69,74.77 97.79,72.86 Q20.S | 99.69,74.77 99.06,75.4 R201.2
N$238
  Top 0.254: D150.A 74.29,86.19 74.93,86.19 Q21.G
  Bottom 0.254: R203.1 73.66,88.1 73.66,86.83 D150.A
N$239
  Top 0.254: Q21.S 78.1,87.46 81.28,90.64 R206.1 80.64,91.27 79.37,91.27 R205.2
N$242
  Top 0.254: Q22.G 95.25,86.19 94.61,86.19 D149.A 93.98,86.83 93.98,88.1 R207.1
N$243
  Top 0.254: Q22.S 97.79,88.1 97.79,89.37 99.06,90.64 R209.2 99.69,91.27 100.96,91.27 R210.1
N$246
  Top 0.254: Q23.G 85.09,70.95 84.45,70.95 D148.A 83.81,71.59 83.81,72.86 R211.1
N$247
  Top 0.254: R213.2 89.53,76.03 90.8,76.03 R214.1
  Bottom 0.254: Q23.S 88.26,72.22 91.44,75.4 R214.1
N$250
  Top 0.254: Q24.G 105.41,70.95 104.77,70.95 D147.A 104.14,71.59 104.14,72.86 R215.1
N$251
  Top 0.254: Q24.S 108.58,72.22 111.76,75.4 R218.1 111.12,76.03 109.85,76.03 R217.2
N$254
  Top 0.254: Q25.G 85.09,86.19 84.45,86.19 D146.A 83.81,86.83 83.81,88.1 R219.1
N$255
  Top 0.254: Q25.S 88.26,87.46 91.44,90.64 R222.1 90.8,91.27 89.53,91.27 R221.2
N$258
  Top 0.254: Q26.G 105.41,86.19 104.77,86.19 D145.A 104.14,86.83 104.14,88.1 R223.1
N$259
  Top 0.254: Q26.S 107.95,88.1 107.95,89.37 109.22,90.64 R225.2 109.85,91.27 111.12,91.27 R226.1
N$262
  Top 0.254: Q27.G 74.93,101.43 74.29,101.43 D160.A 73.66,102.07 73.66,103.34 R227.1
N$263
  Top 0.254: Q27.S 78.1,102.7 81.28,105.88 R230.1 80.64,106.52 79.37,106.52 R229.2
N$266
  Top 0.254: Q28.G 95.25,101.43 94.61,101.43 D159.A 93.98,102.07 93.98,103.34 R231.1
N$267
  Top 0.254: Q28.S 98.42,102.7 101.59,105.88 R234.1 100.96,106.52 99.69,106.52 R233.2
N$270
  Top 0.254: Q29.G 74.93,116.67 74.29,116.67 D158.A 73.66,117.31 73.66,118.58 R235.1
N$271
  Top 0.254: Q29.S 78.1,117.94 81.28,121.12 R238.1 80.64,121.75 79.37,121.75 R237.2
N$274
  Top 0.254: Q30.G 95.25,116.67 94.61,116.67 D157.A 93.98,117.31 93.98,118.58 R239.1
N$275
  Top 0.254: Q30.S 98.42,117.94 101.59,121.12 R242.1 100.96,121.75 99.69,121.75 R241.2
N$278
  Top 0.254: Q31.G 85.09,101.43 84.45,101.43 D156.A 83.81,102.07 83.81,103.34 R243.1
N$279
  Top 0.254: Q31.S 87.62,103.34 87.62,104.61 88.9,105.88 R245.2 89.53,106.52 90.8,106.52 R246.1
N$282
  Top 0.254: Q32.G 105.41,101.43 104.77,101.43 D155.A 104.14,102.07 104.14,103.34 R247.1
N$283
  Top 0.254: Q32.S 108.58,102.7 111.76,105.88 R250.1 111.12,106.52 109.85,106.52 R249.2
N$286
  Top 0.254: Q33.G 85.09,116.67 84.45,116.67 D154.A 83.81,117.31 83.81,118.58 R251.1
N$287
  Bottom 0.254: Q33.S 88.26,117.94 91.44,121.12 R254.1 90.8,121.75 89.53,121.75 R253.2
N$290
  Top 0.254: Q34.G 105.41,116.67 104.77,116.67 D153.A 104.14,117.31 104.14,118.58 R255.1
N$291
  Top 0.254: 109.85,120.48 111.12,121.75 R258.1 | 109.85,120.48 107.95,118.58 Q34.S | 109.85,120.48 109.22,121.12 R257.2
N$294
  Top 0.254: R260.1 132.71,10 133.98,10 R259.2
  Bottom 0.254: Q36.S 132.08,13.17 132.08,10.63 R260.1
N$298
  Top 0.254: R262.1 153.03,25.23 154.3,25.23 R261.2
  Bottom 0.254: Q38.S 152.4,28.41 152.4,25.87 R262.1
N$302
  Top 0.254: R263.2 133.98,25.23 132.71,25.23 R264.1 132.08,25.87 132.08,28.41 Q40.S
N$306
  Top 0.254: R266.1 163.19,10 164.46,10 R265.2
  Bottom 0.254: Q42.S 162.56,13.17 162.56,10.63 R266.1
N$310
  Top 0.254: R267.2 144.14,10 142.87,10 R268.1 142.24,10.63 142.24,13.17 Q44.S
N$314
  Top 0.254: R270.1 163.19,25.23 164.46,25.23 R269.2
  Bottom 0.254: Q46.S 162.56,28.41 162.56,25.87 R270.1
N$318
  Top 0.254: R271.2 144.14,25.23 142.87,25.23 R272.1 142.24,25.87 142.24,28.41 Q48.S
N$322
  Top 0.254: R273.2 133.98,40.48 132.71,40.48 R274.1 132.08,41.11 132.08,43.65 Q50.S
N$326
  Top 0.254: R275.2 154.3,40.48 153.03,40.48 R276.1 152.4,41.11 152.4,43.65 Q52.S
N$330
  Top 0.254: R277.2 133.98,55.72 132.71,55.72 R278.1 132.08,56.35 132.08,58.89 Q54.S
N$334
  Top 0.254: R279.2 154.3,55.72 153.03,55.72 R280.1 152.4,56.35 152.4,58.89 Q56.S
N$338
  Top 0.254: R281.2 144.14,40.48 142.87,40.48 R282.1 142.24,41.11 142.24,43.65 Q58.S
N$342
  Top 0.254: R284.1 163.19,40.48 164.46,40.48 R283.2
  Bottom 0.254: Q60.S 162.56,43.65 162.56,41.11 R284.1
N$346
  Top 0.254: R285.2 144.14,55.72 142.87,55.72 R286.1 142.24,56.35 142.24,58.89 Q62.S
N$350
  Top 0.254: R288.1 163.19,55.72 164.46,55.72 R287.2
  Bottom 0.254: Q64.S 162.56,58.89 162.56,56.35 R288.1
N$354
  Top 0.254: R290.1 132.71,68.41 133.98,68.41 R289.2
  Bottom 0.254: Q66.S 132.08,71.59 132.08,69.05 R290.1
N$358
  Top 0.254: R291.2 144.14,68.41 142.87,68.41 R292.1 142.24,69.05 142.24,71.59 Q68.S
N$362
  Top 0.254: R293.2 133.98,83.65 132.71,83.65 R294.1 132.08,84.29 132.08,86.83 Q70.S
N$366
  Top 0.254: R295.2 144.14,83.65 142.87,83.65 R296.1 142.24,84.29 142.24,86.83 Q72.S
N$370
  Top 0.254: R297.2 154.3,68.41 153.03,68.41 R298.1 152.4,69.05 152.4,71.59 Q74.S
N$374
  Top 0.254: R300.1 163.19,68.41 164.46,68.41 R299.2
  Bottom 0.254: Q76.S 162.56,71.59 162.56,69.05 R300.1
N$378
  Top 0.254: R301.2 154.3,83.65 153.03,83.65 R302.1 152.4,84.29 152.4,86.83 Q78.S
N$382
  Top 0.254: R304.1 163.19,83.65 164.46,83.65 R303.2
  Bottom 0.254: Q80.S 162.56,86.83 162.56,84.29 R304.1
N$386
  Top 0.254: R305.2 133.98,98.89 132.71,98.89 R306.1 132.08,99.53 132.08,102.07 Q82.S
N$390
  Top 0.254: R307.2 144.14,98.89 142.87,98.89 R308.1 142.24,99.53 142.24,102.07 Q84.S
N$394
  Top 0.254: R309.2 133.98,114.13 132.71,114.13 R310.1 132.08,114.77 132.08,117.31 Q86.S
N$398
  Top 0.254: R311.2 154.3,114.13 153.03,114.13 R312.1 152.4,114.77 152.4,117.31 Q88.S
N$402
  Top 0.254: R313.2 154.3,98.89 153.03,98.89 R314.1 152.4,99.53 152.4,102.07 Q90.S
N$406
  Top 0.254: R316.1 163.19,98.89 164.46,98.89 R315.2
  Bottom 0.254: Q92.S 162.56,102.07 162.56,99.53 R316.1
N$410
  Top 0.254: R317.2 144.14,114.13 142.87,114.13 R318.1 142.24,114.77 142.24,117.31 Q94.S
N$414
  Top 0.254: R320.1 163.19,114.13 164.46,114.13 R319.2
  Bottom 0.254: Q96.S 162.56,117.31 162.56,114.77 R320.1
P1  (via drill 0.61)
  Top 0.254: v83.81,37.3 83.18,37.94 78.1,37.94 76.83,39.2 v53.97,39.2 | v113.03,138.27 135.25,138.27 136.52,139.53 SIDE1.30 | v116.2,119.21 112.39,115.4 113.03,114.77 113.03,88.1 v115.56,85.56 | v115.56,81.75 114.3,80.48 114.3,67.78 125.73,56.35 v125.73,52.54 | v89.53,45.55 89.53,44.29 87.62,42.38 Q15.D
  Bottom 0.254: v83.81,37.3 87.62,41.11 Q15.D | v53.97,39.2 51.43,41.74 48.89,41.74 48.25,42.38 R60.1 | Q57.D 144.78,44.92 142.87,43.02 141.6,43.02 140.33,44.29 Q58.D 139.69,44.92 139.69,45.55 135.88,49.37 128.9,49.37 128.27,50 | v113.03,138.27 113.03,133.82 108.58,129.38 108.58,128.11 116.2,120.48 v116.2,119.21 | v115.56,85.56 v115.56,81.75 | v125.73,52.54 128.27,50 | v89.53,45.55 90.8,46.83 113.66,46.83 118.74,41.74 122.55,41.74 128.27,47.46 128.27,50
P2  (via drill 0.61)
  Top 0.254: v46.98,126.2 61.59,126.2 63.49,128.11 73.02,128.11 v73.66,128.74 | v121.92,117.94 128.9,117.94 Q86.D | v119.38,130.01 110.48,130.01 107.31,133.19 v97.15,133.19
  Bottom 0.254: Q86.D 130.17,117.94 131.44,116.67 132.71,116.67 134.62,118.58 Q85.D | 77.47,128.74 77.47,132.55 74.93,135.09 74.93,137.63 73.66,138.9 SIDE2.24 | 77.47,124.93 77.47,128.74 | 77.47,124.93 77.47,121.12 78.73,119.85 78.73,117.31 77.47,116.04 Q29.D | v46.98,126.2 45.71,124.93 36.82,124.93 33.65,121.75 31.11,121.75 R116.1 | 77.47,128.74 v73.66,128.74 | v121.92,117.94 121.92,127.47 v119.38,130.01 | v97.15,133.19 88.26,133.19 86.99,134.46 77.47,124.93
PDA1  (via drill 0.61)
  Top 0.254: v119.38,22.06 114.93,17.62 114.93,10 113.03,8.09 93.98,8.09 92.07,10 D1.C
  Bottom 0.254: D136.C 84.45,10 90.8,10 D1.C | v119.38,22.06 119.38,27.14 SV5.2
PDB1  (via drill 0.61)
  Top 0.254: D135.C 74.29,10 80.64,10 D4.C | v111.76,23.33 106.68,23.33 105.41,22.06 v83.81,22.06
  Bottom 0.254: v111.76,23.33 118.74,30.32 SV5.4 | v83.81,22.06 80.01,18.25 80.01,11.9 81.28,10.63 D4.C
PDC1  (via drill 0.61)
  Top 0.254: D134.C 94.61,25.23 100.96,25.23 D5.C | v118.11,24.6 118.11,30.95 119.38,32.22 SV5.6
  Bottom 0.254: v118.11,24.6 118.11,16.98 120.01,15.08 118.74,13.81 117.47,13.81 108.58,22.7 104.77,22.7 102.23,25.23 D5.C
PDD1
  Top 0.254: D133.C 74.29,25.23 80.64,25.23 D8.C
  Bottom 0.254: SV5.8 118.74,35.4 117.47,35.4 116.2,34.12 95.88,34.12 95.25,33.49 95.25,32.22 94.61,31.59 93.34,31.59 92.7,30.95 92.7,29.68 92.07,29.05 89.53,29.05 88.26,30.32 85.72,30.32 84.45,29.05 83.18,29.05 82.55,28.41 82.55,27.14 81.28,25.87 D8.C
PDD2  (via drill 0.61)
  Top 0.254: D151.C 94.61,68.41 100.96,68.41 D52.C 102.23,68.41 103.5,67.14 104.77,67.14 107.95,63.97 107.95,61.43 v109.85,59.52 | v122.55,81.75 123.19,82.38 123.19,89.37 122.55,90 121.28,90 120.01,88.73 SV6.4
  Bottom 0.254: v122.55,81.75 122.55,69.68 112.39,59.52 v109.85,59.52
PDE1
  Top 0.254: D132.C 104.77,10 111.12,10 D7.C 111.76,10.63 113.66,12.54 113.66,18.89 121.92,27.14 SV5.1
PDE2  (via drill 0.61)
  Top 0.254: v116.84,88.1 119.38,90.64 SV6.6
  Bottom 0.254: D150.C 74.29,83.65 80.64,83.65 D53.C 81.91,83.65 83.81,81.75 113.03,81.75 114.3,83.02 114.3,85.56 v116.84,88.1
PDF1
  Top 0.254: D131.C 94.61,10 100.96,10 D40.C 102.23,10 103.5,8.73 112.39,8.73 114.3,10.63 114.3,18.25 123.19,27.14 123.19,28.41 121.92,29.68 SV5.3
PDF2  (via drill 0.61)
  Top 0.254: D149.C 94.61,83.65 100.96,83.65 D54.C | v114.3,90.64 v116.84,90.64
  Bottom 0.254: v116.84,90.64 119.38,93.18 SV6.8 | v114.3,90.64 115.56,91.91 114.3,93.18 104.14,93.18 102.87,91.91 102.87,88.1 102.23,87.46 100.96,87.46 100.33,86.83 100.33,85.56 101.59,84.29 D54.C
PDH1
  Bottom 0.254: D130.C 104.77,25.23 111.12,25.23 D41.C 112.39,25.23 118.74,31.59 120.01,31.59 121.28,32.86 SV5.5
PDH2
  Bottom 0.254: D148.C 84.45,68.41 90.8,68.41 D55.C 92.07,68.41 93.34,67.14 112.39,67.14 113.66,68.41 113.66,77.3 121.92,85.56 SV6.1
PDJ1  (via drill 0.61)
  Top 0.254: D129.C 84.45,25.23 90.8,25.23 D42.C 91.44,25.87 92.7,27.14 v92.7,34.12
  Bottom 0.254: v92.7,34.12 95.25,36.66 120.01,36.66 121.28,35.4 SV5.7
PDJ2
  Top 0.254: SV6.3 121.28,88.73 120.01,87.46 118.74,87.46 113.66,82.38 113.66,70.95 111.76,69.05 D56.C
  Bottom 0.254: D147.C 104.77,68.41 111.12,68.41 D56.C
PDK1  (via drill 0.61)
  Top 0.254: v116.2,35.4 118.74,37.94 SV5.10 | v112.39,35.4 112.39,37.3 v109.22,40.48 | v95.88,40.48 94.61,39.2 83.18,39.2 81.91,40.48 D43.C
  Bottom 0.254: D144.C 73.66,41.11 72.39,42.38 72.39,43.65 73.02,44.29 75.56,44.29 76.83,45.55 78.1,45.55 79.37,44.29 79.37,41.74 80.64,40.48 D43.C | v112.39,35.4 v116.2,35.4 | v109.22,40.48 106.04,40.48 104.77,41.74 99.69,41.74 98.42,40.48 v95.88,40.48
PDK2
  Top 0.254: D146.C 84.45,83.65 90.8,83.65 D57.C
  Bottom 0.254: SV6.5 121.28,91.27 120.01,90 117.47,90 113.66,86.19 113.66,83.65 112.39,82.38 93.34,82.38 92.07,83.65 D57.C
PDL1
  Bottom 0.254: D143.C 94.61,40.48 95.88,39.2 99.69,39.2 100.96,40.48 D44.C 102.23,40.48 104.14,38.57 111.76,38.57 113.66,40.48 118.74,40.48 SV5.12
PDL2  (via drill 0.61)
  Top 0.254: v114.93,88.73 v116.84,86.83
  Bottom 0.254: D145.C 104.77,83.65 111.12,83.65 D58.C 111.76,84.29 113.03,85.56 113.03,86.83 v114.93,88.73 | v116.84,86.83 117.47,87.46 122.55,87.46 123.19,88.1 123.19,91.91 121.92,93.18 SV6.7
PDM1  (via drill 0.61)
  Top 0.254: v113.66,65.88 115.56,63.97 115.56,56.35 113.66,54.45 113.66,48.09 118.74,43.02 SV5.14
  Bottom 0.254: 76.2,65.24 73.66,65.24 72.39,63.97 72.39,62.7 70.48,60.8 70.48,58.26 73.02,55.72 D142.C | 76.2,65.24 77.47,63.97 77.47,62.7 80.01,60.16 80.01,57.62 81.28,56.35 D45.C | v113.66,65.88 84.45,65.88 82.55,67.78 82.55,71.59 81.91,72.22 80.64,72.22 78.73,70.32 78.73,67.78 76.2,65.24
PDM2  (via drill 0.61)
  Top 0.254: D160.C 74.29,98.89 80.64,98.89 D59.C | v115.56,93.18 118.74,96.35 SV6.10 | v86.36,93.18 v102.87,93.18
  Bottom 0.254: v115.56,93.18 114.93,93.81 103.5,93.81 v102.87,93.18 | v86.36,93.18 81.28,98.26 D59.C
PDN1  (via drill 0.61)
  Top 0.254: D141.C 94.61,55.72 100.96,55.72 D46.C 101.59,56.35 102.87,57.62 102.87,61.43 103.5,62.06 v105.41,62.06 | v114.3,63.97 v114.3,56.35
  Bottom 0.254: v114.3,56.35 123.19,47.46 123.19,44.92 122.55,44.29 121.28,44.29 120.01,45.55 SV5.16 | v114.3,63.97 113.03,63.97 112.39,64.6 106.04,64.6 105.41,63.97 v105.41,62.06
PDN2
  Top 0.254: D159.C 94.61,98.89 95.25,98.26 101.59,98.26 D60.C
  Bottom 0.254: SV6.12 118.74,98.89 115.56,95.72 105.41,95.72 102.23,98.89 D60.C
PDP1
  Top 0.254: D140.C 84.45,40.48 90.8,40.48 D47.C
  Bottom 0.254: SV5.9 121.28,37.94 120.01,39.2 113.66,39.2 112.39,37.94 94.61,37.94 92.07,40.48 D47.C
PDP2
  Top 0.254: D158.C 74.29,114.13 80.64,114.13 D61.C
  Bottom 0.254: SV6.14 118.74,101.43 108.58,111.59 84.45,111.59 81.91,114.13 D61.C
PDR1  (via drill 0.61)
  Top 0.254: v113.66,41.74 120.01,41.74 121.28,40.48 SV5.11
  Bottom 0.254: D139.C 104.77,40.48 106.04,39.2 109.85,39.2 111.12,40.48 D48.C 112.39,40.48 v113.66,41.74
PDR2
  Top 0.254: D157.C 94.61,114.13 100.96,114.13 D62.C
  Bottom 0.254: SV6.16 119.38,104.61 111.12,112.86 103.5,112.86 102.23,114.13 D62.C
PDS1  (via drill 0.61)
  Top 0.254: D138.C 84.45,55.72 90.8,55.72 D49.C 91.44,55.08 93.98,52.54 v111.76,52.54
  Bottom 0.254: v111.76,52.54 117.47,46.83 117.47,45.55 118.74,44.29 120.01,44.29 121.28,43.02 SV5.13
PDS2  (via drill 0.61)
  Top 0.254: v114.93,97.62 120.01,97.62 121.28,96.35 SV6.9 | v105.41,96.99 95.25,96.99 v94.61,96.35
  Bottom 0.254: D156.C 84.45,98.89 90.8,98.89 D63.C 92.07,98.89 v94.61,96.35 | v114.93,97.62 113.66,97.62 112.39,96.35 106.04,96.35 v105.41,96.99
PDT2
  Bottom 0.254: D155.C 104.77,98.89 111.12,98.89 D64.C 112.39,98.89 113.66,100.16 120.01,100.16 121.28,98.89 SV6.11
PDU1
  Top 0.254: D137.C 104.77,55.72 111.12,55.72 D50.C
  Bottom 0.254: SV5.15 121.28,45.55 111.76,55.08 D50.C
PDU2
  Top 0.254: D154.C 84.45,114.13 90.8,114.13 D65.C
  Bottom 0.254: SV6.13 121.28,101.43 120.01,102.7 118.74,102.7 109.22,112.23 93.98,112.23 92.07,114.13 D65.C
PDV1  (via drill 0.61)
  Top 0.254: D152.C 74.29,68.41 80.64,68.41 D51.C | v119.38,81.75 119.38,85.56 SV6.2
  Bottom 0.254: v119.38,81.75 119.38,70.32 113.66,64.6 113.03,65.24 83.81,65.24 81.28,67.78 D51.C
PDV2
  Bottom 0.254: D153.C 104.77,114.13 111.12,114.13 D66.C 111.76,113.5 121.28,103.97 SV6.15
PGA1
  Top 0.254: D3.C 153.03,17.62 156.21,17.62 Q1.G
  Bottom 0.254: SV3.2 176.53,27.14 168.27,18.89 158.75,18.89 156.84,16.98 Q1.G
PGB1  (via drill 0.61)
  Top 0.254: D67.C 132.71,17.62 135.88,17.62 Q35.G 136.52,16.98 138.43,18.89 156.21,18.89 v158.75,16.35
  Bottom 0.254: v158.75,16.35 158.75,9.36 159.38,8.73 163.19,8.73 163.83,9.36 163.83,10.63 164.46,11.27 168.27,11.27 170.81,13.81 175.89,13.81 189.22,27.14 189.22,28.41 188.59,29.05 184.78,29.05 182.24,31.59 178.43,31.59 177.16,30.32 SV3.4
PGC1
  Top 0.254: D69.C 153.03,32.86 156.21,32.86 Q37.G 156.84,32.22 158.75,34.12 166.37,34.12 167.63,32.86 175.89,32.86 SV3.6
PGD1  (via drill 0.61)
  Top 0.254: D71.C 132.71,32.86 135.88,32.86 Q39.G 136.52,32.22 138.43,34.12 v146.05,34.12
  Bottom 0.254: v146.05,34.12 147.31,32.86 147.31,32.22 148.59,30.95 148.59,24.6 150.49,22.7 167,22.7 169.54,25.23 169.54,27.78 176.53,34.76 SV3.8
PGD2
  Top 0.254: D99.C 142.87,76.03 146.05,76.03 Q67.G
  Bottom 0.254: SV1.4 175.89,88.73 167.63,80.48 151.76,80.48 146.68,75.4 Q67.G
PGE1
  Bottom 0.254: D73.C 162.56,16.98 165.73,16.98 Q41.G 167,16.98 167.63,16.98 178.43,27.78 SV3.1
PGE2  (via drill 0.61)
  Top 0.254: 135.25,91.27 135.88,91.27 Q69.G | 135.25,91.27 132.71,91.27 D101.C | v169.54,84.92 v166.37,84.92 | v140.97,95.72 139.69,95.72 135.25,91.27
  Bottom 0.254: v169.54,84.92 175.89,91.27 SV1.6 | v166.37,84.92 164.46,84.92 163.83,84.29 163.83,83.02 163.19,82.38 161.92,82.38 161.28,83.02 161.28,84.29 158.75,86.83 158.75,90 154.3,94.45 142.24,94.45 v140.97,95.72
PGF1
  Top 0.254: D75.C 142.87,17.62 146.05,17.62 Q43.G
  Bottom 0.254: SV3.3 178.43,30.32 177.16,29.05 174.62,29.05 165.73,20.16 149.86,20.16 146.68,16.98 Q43.G
PGF2
  Top 0.254: D103.C 142.87,91.27 146.05,91.27 Q71.G 146.68,90.64 149.22,93.18 161.28,93.18 163.19,95.08 170.18,95.08 171.44,93.81 175.89,93.81 SV1.8
PGH1
  Top 0.254: D77.C 163.19,32.86 166.37,32.86 Q45.G 166.37,31.59 177.16,31.59 178.43,32.86 SV3.5
PGH2  (via drill 0.61)
  Top 0.254: D105.C 153.03,76.03 156.21,76.03 Q73.G | v172.08,83.65 175.89,83.65 178.43,86.19 SV1.1
  Bottom 0.254: v172.08,83.65 165.73,77.3 158.75,77.3 156.84,75.4 Q73.G
PGJ1
  Top 0.254: D79.C 142.87,32.86 146.05,32.86 Q47.G 146.68,32.22 151.12,36.66 177.16,36.66 178.43,35.4 SV3.7
PGJ2
  Top 0.254: D107.C 163.19,76.03 166.37,76.03 Q75.G
  Bottom 0.254: SV1.3 179.06,88.1 177.8,86.83 177.8,85.56 167.63,75.4 167,75.4 Q75.G
PGK1  (via drill 0.61)
  Top 0.254: D81.C 132.71,48.09 135.88,48.09 Q49.G | v167,37.94 175.89,37.94 SV3.10 | v149.86,37.94 137.79,37.94 v137.16,38.57
  Bottom 0.254: v167,37.94 159.38,37.94 158.11,36.66 151.12,36.66 v149.86,37.94 | v137.16,38.57 135.88,39.84 135.88,46.83 Q49.G
PGK2  (via drill 0.61)
  Top 0.254: D109.C 153.03,91.27 156.21,91.27 Q77.G 156.84,90.64 158.75,92.54 161.92,92.54 163.19,93.81 v170.18,93.81
  Bottom 0.254: v170.18,93.81 171.44,92.54 177.16,92.54 178.43,91.27 SV1.5
PGL1  (via drill 0.61)
  Top 0.254: D83.C 153.03,48.09 156.21,48.09 Q51.G | v173.35,43.02 175.89,40.48 SV3.12
  Bottom 0.254: v173.35,43.02 167,49.37 158.75,49.37 156.84,47.46 Q51.G
PGL2
  Top 0.254: D111.C 162.56,90.64 165.73,90.64 Q79.G 167,90.64 168.91,92.54 177.16,92.54 178.43,93.81 SV1.7
PGM1  (via drill 0.61)
  Top 0.254: D85.C 132.71,63.34 135.88,63.34 Q53.G | v172.72,50 172.72,47.46 176.53,43.65 SV3.14 | v167,53.18 163.83,50 158.11,50 157.47,50.63 153.03,50.63 151.76,49.37 v143.5,49.37 | v138.43,49.37 138.43,51.91 v135.88,54.45
  Bottom 0.254: v172.72,50 169.54,53.18 v167,53.18 | v138.43,49.37 v143.5,49.37 | v135.88,54.45 135.88,62.06 Q53.G
PGM2  (via drill 0.61)
  Top 0.254: D113.C 132.71,106.52 135.88,106.52 Q81.G | v170.18,108.42 169.54,107.78 169.54,102.7 175.89,96.35 SV1.10 | v167.63,110.96 v137.16,110.96
  Bottom 0.254: v170.18,108.42 v167.63,110.96 | v137.16,110.96 132.71,106.52 D113.C
PGN1
  Top 0.254: D87.C 153.03,63.34 156.21,63.34 Q55.G
  Bottom 0.254: SV3.16 175.89,45.55 172.08,45.55 167.63,50 163.83,50 158.75,55.08 158.75,61.43 157.47,62.7 156.84,62.7 Q55.G
PGN2  (via drill 0.61)
  Top 0.254: D115.C 142.87,106.52 146.05,106.52 Q83.G 146.68,105.88 148.59,107.78 156.84,107.78 158.75,109.69 v167.63,109.69 | v170.81,106.52 170.81,105.24 176.53,99.53 SV1.12
  Bottom 0.254: v167.63,109.69 v170.81,106.52
PGP1  (via drill 0.61)
  Top 0.254: D89.C 142.87,48.09 146.05,48.09 Q57.G | v167.63,35.4 v170.18,35.4
  Bottom 0.254: v170.18,35.4 171.44,36.66 177.16,36.66 178.43,37.94 SV3.9 | v167.63,35.4 149.86,35.4 146.05,39.2 146.05,46.83 Q57.G
PGP2  (via drill 0.61)
  Top 0.254: D117.C 132.71,121.75 135.88,121.75 Q85.G | v168.27,124.29 176.53,116.04 176.53,114.77 175.25,113.5 173.99,113.5 172.08,111.59 172.08,106.52 176.53,102.07 SV1.14
  Bottom 0.254: v168.27,124.29 130.17,124.29 127.63,121.75 127.63,114.13 128.9,112.86 135.25,112.86 135.88,113.5 135.88,120.48 Q85.G
PGR1
  Top 0.254: D91.C 163.19,48.09 166.37,48.09 Q59.G
  Bottom 0.254: SV3.11 178.43,40.48 177.16,41.74 173.35,41.74 167.63,47.46 167,47.46 Q59.G
PGR2
  Top 0.254: D119.C 153.03,121.75 156.21,121.75 Q87.G
  Bottom 0.254: SV1.16 175.89,103.97 172.08,103.97 163.19,112.86 156.84,112.86 156.21,113.5 156.21,120.48 Q87.G
PGS1  (via drill 0.61)
  Top 0.254: D93.C 142.87,63.34 146.05,63.34 Q61.G | v162.56,52.54 160.65,52.54 160.02,53.18 147.95,53.18 v147.31,53.81
  Bottom 0.254: v162.56,52.54 164.46,50.63 168.27,50.63 172.08,46.83 177.16,46.83 177.8,46.19 177.8,44.92 179.06,43.65 SV3.13 | v147.31,53.81 146.05,55.08 146.05,62.06 Q61.G
PGS2  (via drill 0.61)
  Top 0.254: D121.C 153.03,106.52 156.21,106.52 Q89.G | v170.81,103.97 170.81,102.7 175.89,97.62 177.16,97.62 178.43,96.35 SV1.9
  Bottom 0.254: v170.81,103.97 164.46,110.32 156.84,110.32 153.03,106.52 D121.C
PGT2
  Top 0.254: D123.C 163.19,106.52 166.37,106.52 Q91.G
  Bottom 0.254: SV1.11 178.43,98.89 177.16,100.16 173.35,100.16 167.63,105.88 167,105.88 Q91.G
PGU1
  Top 0.254: D95.C 163.19,63.34 166.37,63.34 Q63.G 167,62.7 167.63,62.7 179.06,51.27 179.06,46.19 SV3.15
PGU2  (via drill 0.61)
  Top 0.254: D125.C 142.87,121.75 146.05,121.75 Q93.G | v169.54,120.48 v169.54,117.94
  Bottom 0.254: v169.54,117.94 177.8,109.69 177.8,103.34 179.06,102.07 SV1.13 | v169.54,120.48 167,123.02 148.59,123.02 146.68,121.12 Q93.G
PGV1  (via drill 0.61)
  Top 0.254: D97.C 132.71,76.03 135.88,76.03 Q65.G 136.52,75.4 138.43,77.3 145.41,77.3 147.95,79.84 v169.54,79.84
  Bottom 0.254: v169.54,79.84 175.89,86.19 SV1.2
PGV2
  Top 0.254: D127.C 163.19,121.75 166.37,121.75 Q95.G
  Bottom 0.254: SV1.15 179.06,104.61 179.06,109.69 167.63,121.12 167,121.12 Q95.G
PUA1\  (via drill 0.61)
  Top 0.254: Q2.G 151.76,15.71 152.4,15.71 153.66,14.44 153.66,11.9 154.3,11.27 155.57,11.27 156.84,12.54 D6.C | v172.72,24.6 179.06,24.6 182.24,27.78 184.78,27.78 SV4.2
  Bottom 0.254: v172.72,24.6 167.63,19.52 156.21,19.52 152.4,15.71 151.76,15.71 Q2.G
PUB1\  (via drill 0.61)
  Top 0.254: v182.24,34.12 184.78,36.66 188.59,36.66 189.86,35.4 189.86,26.51 188.59,25.23 184.78,25.23 167.63,8.09 137.16,8.09 135.88,9.36 135.88,10.63 137.16,11.9 D68.C
  Bottom 0.254: Q36.G 131.44,15.71 132.08,15.71 133.98,13.81 135.25,13.81 136.52,12.54 D68.C | v182.24,34.12 185.41,30.95 SV4.4
PUC1\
